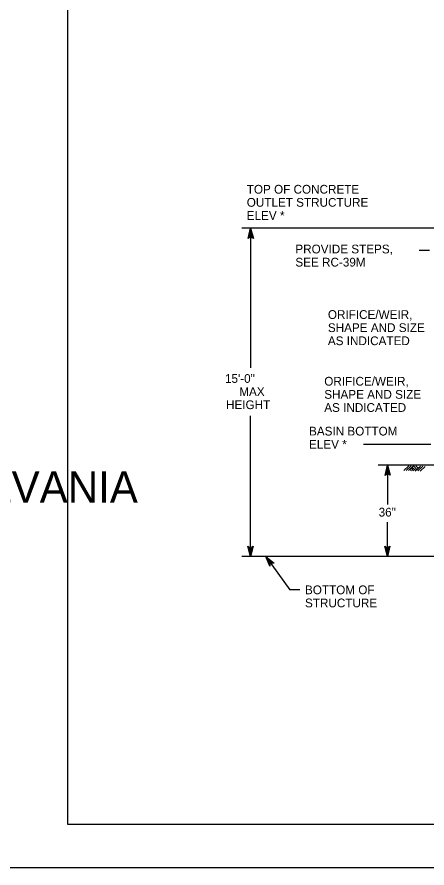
# Model space of a CAD drawing. Extents: x 636462 to 639890, y 299944 to 300538.
# Drawn here: x 639007.7 to 639148.1, y 299944.4 to 300236.1 of the extents above; entities that cross this region are included whole.
import ezdxf

# ---------------------------------------------------------------- set-up
doc = ezdxf.new("R2010")
doc.units = 0
for name, color, linetype in [('1', 7, 'Continuous'), ('Default', 7, 'Continuous'), ('PLT-BNDY', 7, 'Continuous')]:
    doc.layers.add(name, color=color, linetype=linetype)

msp = doc.modelspace()

# ---------------------------------------------------------------- linework, layer by layer
at = {"layer": '1'}
msp.add_lwpolyline([(639810.91, 299959.45), (639810.91, 300523.45), (639024.91, 300523.45), (639024.91, 299959.45), (639810.91, 299959.45), (639810.91, 299985.81), (639610.91, 299985.81), (639610.91, 300050.49), (639810.91, 300050.49), (639810.91, 300079.45), (639610.91, 300079.45), (639610.91, 299959.45), (639689.72, 299959.45), (639689.72, 299985.81), (639689.72, 299959.45), (639766.72, 299959.45), (639766.72, 299985.81), (639766.72, 299973.49), (639810.91, 299973.49)], dxfattribs=at)
at = {"layer": 'Default'}
for p, q in [((639163.38, 300163.65), (639084.63, 300163.65)), ((639087.71, 300163.65), (639087.71, 300115.87)), ((639145.5, 300156.21), (639149, 300156.21)), ((639087.71, 300051.22), (639087.71, 300099.39)), ((639126.35, 300089.67), (639149.47, 300089.67)), ((639165.5, 300082.47), (639131.4, 300082.47)), ((639134.59, 300082.49), (639134.59, 300069.02)), ((639140.2, 300080.67), (639141.93, 300082.28)), ((639140.98, 300080.64), (639142.72, 300082.26)), ((639141.79, 300080.61), (639143.53, 300082.23)), ((639142.7, 300081.46), (639143.55, 300080.55)), ((639143.07, 300081.81), (639144.19, 300080.61)), ((639143.49, 300082.24), (639144.64, 300081.01)), ((639144.12, 300080.53), (639145.87, 300082.16)), ((639144.3, 300082.21), (639145.05, 300081.41)), ((639144.97, 300080.5), (639146.69, 300082.1)), ((639145.78, 300080.47), (639147.5, 300082.08)), ((639142.28, 300081.07), (639142.77, 300080.55)), ((639134.59, 300051.22), (639134.59, 300062.97)), ((639163.38, 300051.22), (639084.63, 300051.22)), ((639092.94, 300051.22), (639101.08, 300039.76)), ((639104.58, 300039.76), (639101.08, 300039.76))]:
    msp.add_line(p, q, dxfattribs=at)
for points in [[(639087.12, 300160.4), (639086.9, 300160.13), (639087.71, 300163.65), (639087.12, 300160.4), (639087.49, 300160.61), (639087.71, 300163.65), (639088.01, 300160.62), (639088.39, 300160.44), (639087.71, 300163.65), (639088.65, 300160.16), (639088.39, 300160.44)], [(639134, 300079.25), (639133.78, 300078.98), (639134.59, 300082.49), (639134, 300079.25), (639134.37, 300079.45), (639134.59, 300082.49), (639134.89, 300079.47), (639135.27, 300079.29), (639134.59, 300082.49), (639135.53, 300079.01), (639135.27, 300079.29)], [(639088.32, 300054.46), (639088.54, 300054.73), (639087.71, 300051.22), (639088.32, 300054.46), (639087.95, 300054.26), (639087.71, 300051.22), (639087.42, 300054.25), (639087.05, 300054.42), (639087.71, 300051.22), (639086.79, 300054.71), (639087.05, 300054.42)], [(639135.19, 300054.46), (639135.41, 300054.73), (639134.59, 300051.22), (639135.19, 300054.46), (639134.82, 300054.26), (639134.59, 300051.22), (639134.3, 300054.25), (639133.92, 300054.42), (639134.59, 300051.22), (639133.67, 300054.7), (639133.92, 300054.42)], [(639094.32, 300048.23), (639094.29, 300047.88), (639092.94, 300051.22), (639094.32, 300048.23), (639094.5, 300048.61), (639092.94, 300051.22), (639094.92, 300048.92), (639095.34, 300048.99), (639092.94, 300051.22), (639095.71, 300048.91), (639095.34, 300048.99)]]:
    msp.add_lwpolyline(points, dxfattribs=at)
at = {"layer": 'PLT-BNDY'}
msp.add_lwpolyline([(638984.91, 300538.45), (639825.91, 300538.45), (639825.91, 299944.45), (638984.91, 299944.45)], close=True, dxfattribs=at)

# ---------------------------------------------------------------- texts
at = {"layer": '1'}
msp.add_text('COMMONWEALTH OF PENNSYLVANIA', height=10.7834, dxfattribs=at).set_placement((638783.07, 300069.59))
at = {"layer": 'Default'}
for s, p in [('TOP OF CONCRETE', (639086.37, 300175.53)), ('OUTLET STRUCTURE', (639086.37, 300171.04)), ('ELEV *', (639086.37, 300166.54)), ('PROVIDE STEPS,', (639103.03, 300155.05)), ('SEE RC-39M', (639103.03, 300150.55)), ('ORIFICE/WEIR,', (639114.17, 300132.6)), ('SHAPE AND SIZE', (639114.17, 300128.1)), ('AS INDICATED', (639114.17, 300123.61)), ('15\'-0"', (639078.91, 300110.68)), ('ORIFICE/WEIR,', (639112.93, 300109.74)), ('MAX', (639083.81, 300106.18)), ('SHAPE AND SIZE', (639112.93, 300105.24)), ('HEIGHT', (639079.27, 300101.69)), ('AS INDICATED', (639112.93, 300100.74)), ('BASIN BOTTOM', (639107.71, 300092.65)), ('ELEV *', (639107.71, 300088.15)), ('36"', (639131.56, 300064.88)), ('BOTTOM OF', (639106.33, 300038.26)), ('STRUCTURE', (639106.33, 300033.77))]:
    msp.add_text(s, height=2.998, dxfattribs=at).set_placement(p)

doc.saveas('drawing.dxf')
